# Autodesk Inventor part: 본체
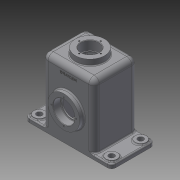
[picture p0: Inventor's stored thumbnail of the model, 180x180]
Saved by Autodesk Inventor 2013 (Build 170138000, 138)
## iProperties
Created: 2010-03
Part Number: 본체
Document SubType Name: Modeling
Designer: 진현석
Density: 1 g/cm^3
Material: 일반
Author: 진현석
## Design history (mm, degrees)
sketch "스케치1"
  geometry: L1 (-62, 52)-(62, 52); L2 (62, 52)-(62, -52); L3 (62, -52)-(-62, -52); L4 (-62, -52)-(-62, 52); 3 further points
  constraints: 8 end point, 2 midpoint, 2 parallel, 1 horizontal, 1 horizontal alignment, 1 perpendicular, 1 vertical alignment
  dimensions: "d0" = 124 distance of L1.start L1.end; "d1" = 104 distance of L1.end L2.end
extrude "돌출1" new body sketch "스케치1" distance "d2" = 164; taper "d3" = 0 deg
fillet "모깎기9" dims "d55" = 13
feature "쉘2" dims "d54" = 10
sketch "스케치2"
  geometry: L1 (124, 0)-(0, 0) reference; C1 r 38 at (62, 75); 2 further points
  constraints: 1 centre point, 1 midpoint, 1 vertical alignment
  dimensions: "d5" = 76 diameter of C1; "d6" = 75 distance from line of L1 C1.centre
extrude "돌출2" join sketch "스케치2" distance "d7" = 11; taper "d8" = 0 deg
sketch "스케치13"
  geometry: L1 (-63, 37)-(-63, 113) reference; L2 (63, 37)-(63, 113) reference; L3 (-63, 75)-(63, 75); L4 (-63, 101)-(-46, 101); L5 (-45, 100)-(-45, 98); L6 (-45, 98)-(45, 98); L7 (45, 98)-(45, 100); L8 (46, 101)-(63, 101); L9 (-42, 0)-(-42, 151) reference; L10 (42, 151)-(42, 0) reference; A1 r 1 centre (46, 100) between (46, 101) and (45, 100); A2 r 1 centre (-46, 100) between (-45, 100) and (-46, 101); 1 further point
  constraints: 12 end point, 4 point on circle, 4 tangent, 3 parallel, 2 centre point, 2 midpoint, 2 perpendicular, 2 point on line, 1 collinear, 1 equal radius
  dimensions: "d77" = 3 distance between parallel lines of L5 L9; "d78" = 3 distance between parallel lines of L10 L7; "d79" = 52 diameter of L8 L3; "d80" = 3 distance between parallel lines of L6 L8; "d81" = 1 radius of A1
revolve "회전1" sketch "스케치13" stored, may be unused: angle "d82" = 90 deg
sketch "스케치4"
  geometry: L1 (62, 52)-(-62, 52) reference; L2 (-62, -52)-(62, -52) reference; L3 (-104, 52)-(104, 52); L4 (104, 52)-(104, -52); L5 (104, -52)-(-104, -52); L6 (-104, -52)-(-104, 52); L7 (-62, 39)-(-62, -39) reference; L8 (62, -39)-(62, 39) reference; A1 r 13 centre (-49, 39) between (-49, 52) and (-62, 39) reference; A2 r 13 centre (-49, -39) between (-62, -39) and (-49, -52) reference; A3 r 13 centre (49, -39) between (49, -52) and (62, -39) reference; A4 r 13 centre (49, 39) between (62, 39) and (49, 52) reference; 2 further points
  constraints: 8 end point, 2 collinear, 2 midpoint, 2 parallel, 1 horizontal, 1 perpendicular
  dimensions: "d11" = 208 distance of L4.end L5.end
extrude "돌출4" join sketch "스케치4" distance "d12" = 10; taper "d13" = 0 deg
sketch "스케치12"
  geometry: L1 (104, -52)-(49, -52) reference; L2 (104, 52)-(104, -52) reference; C1 r 13.5 at (87, -35); 1 further point
  constraints: 1 centre point
  dimensions: "d57" = 27 diameter of C1; "d58" = 17 distance from line of L1 C1.centre; "d59" = 17 distance from line of L2 C1.centre
extrude "돌출10" join sketch "스케치12" distance "d60" = 3; taper "d61" = 0 deg
hole "구멍2" diameter "d64" = 13.5; stored, may be unused: countersink angle "d68" = 90 deg, drill point angle "d70" = 118 deg; dims "d62" = 10, "d63" = 10, "d65" = 6, "d66" = 33, "d67" = 8.6, "d69" = 8
sketch "스케치9"
  geometry: C1 r 35 at (0, 0); 1 further point
  constraints: 1 centre point, 1 coincident
  dimensions: "d43" = 70 diameter of C1
extrude "돌출11" join sketch "스케치9" distance "d71" = 14; taper "d72" = 0 deg
sketch "스케치7"
  geometry: C1 r 21.5 at (0, 0); C2 r 35 at (0, 0) reference; 1 further point
  constraints: 1 centre point, 1 coincident, 1 concentric
  dimensions: "d23" = 43 diameter of C1
extrude "돌출12" cut sketch "스케치7" distance "d73" = 22; taper "d74" = 0 deg
sketch "스케치8"
  geometry: C1 r 38 at (0, 0) reference; 2 further points
  constraints: 1 vertical alignment
  dimensions: "d32" = 30 distance of C1.centre point (0, 30)
hole "구멍1" sketch "스케치8" at (0, 30) diameter "d33" = 3.242; stored, may be unused: countersink angle "d37" = 90 deg, drill point angle "d39" = 118 deg; dims "d34" = 8, "d35" = 4, "d36" = 2, "d38" = 10
fillet "모깎기1" dims "d26" = 10
fillet "모깎기10" dims "d75" = 3
fillet "모깎기11" dims "d76" = 3
fillet "모깎기7" dims "d50" = 3
chamfer "모따기2" distance "d83" = 1; stored, may be unused: second distance "d84" = 2, angle "d85" = 45 deg
chamfer "모따기3" distance "d86" = 1; stored, may be unused: second distance "d87" = 2, angle "d88" = 45 deg
fillet "모깎기12" dims "d89" = 2
sketch "스케치14"
  geometry: C1 r 19.5 at (0, 0); C2 r 21.5 at (0, 0) reference; 1 further point
  constraints: 1 centre point, 1 coincident
  dimensions: "d92" = 2 radial gap between concentric circles of C2 C1
extrude "돌출13" cut sketch "스케치14" stored distance "d93" = 10; taper "d94" = 0 deg
sketch "스케치15"
  geometry: C1 r 2.25 at (0, 26) reference; 1 further point
hole "구멍3" sketch "스케치15" at (0, 26) diameter "d95" = 3.242; stored, may be unused: countersink angle "d99" = 90 deg, drill point angle "d101" = 118 deg; dims "d96" = 8, "d97" = 4, "d98" = 2, "d100" = 10
sketch "스케치16"
  geometry: L1 (143, -151)-(-45, -151) reference; L2 (98, 13)-(0, 13) reference; 3 further points
  constraints: 1 midpoint, 1 vertical alignment, 1 other
  dimensions: "d105" = 20 distance from line of point (49, -7) L2
feature "엠보싱1" sketch "스케치16" dims "d0" = 124, "d1" = 104, "d106" = 0.5, "d107" = 0
node "솔리드1"
mirror "대칭1"
mirror "대칭5"
mirror "대칭6"
pattern_circular "원형 패턴1" dims angle "d41" = 360 deg
mirror "대칭4"
pattern_circular "원형 패턴2" dims angle "d103" = 360 deg
node "참조1"
